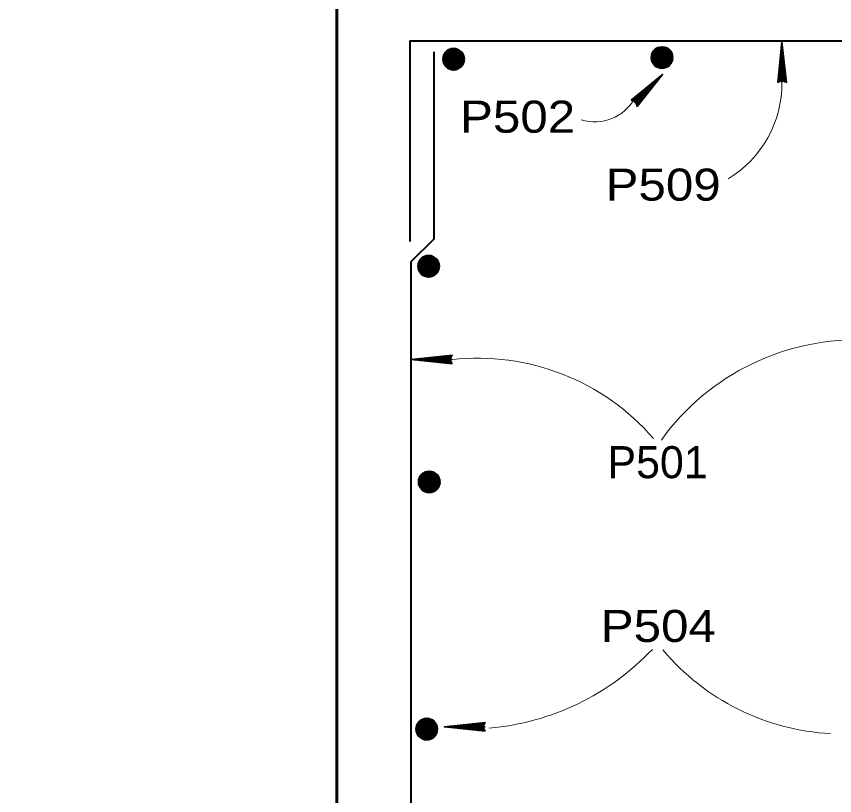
# Model space of a CAD drawing. Extents: x 14.14 to 17.34, y -1.61 to 0.38.
# Drawn here: x 15.5046 to 15.7173, y -1.0834 to -0.8807 of the extents above; entities that cross this region are included whole.
import ezdxf

# ---------------------------------------------------------------- set-up
doc = ezdxf.new("R2010")
doc.units = 0
doc.header["$LTSCALE"] = 0.0033
doc.layers.add('1', color=7, linetype='Continuous', lineweight=40)

msp = doc.modelspace()

# ---------------------------------------------------------------- linework, layer by layer
at = {"layer": '1'}
for p, q in [((15.67475, -0.89025), (15.6735, -0.889083)), ((15.616167, -0.890333), (15.62075, -0.8925)), ((15.616417, -0.89075), (15.620333, -0.8915)), ((15.616417, -0.890917), (15.620333, -0.891667)), ((15.616417, -0.891167), (15.62025, -0.891917)), ((15.6165, -0.890333), (15.620417, -0.891)), ((15.6165, -0.8905), (15.620417, -0.89125)), ((15.616583, -0.89), (15.620417, -0.890667)), ((15.6185, -0.890833), (15.619833, -0.889833)), ((15.620583, -0.890667), (15.619333, -0.8895)), ((15.670333, -0.889917), (15.674917, -0.892083)), ((15.6705, -0.890917), (15.674333, -0.891583)), ((15.6705, -0.891083), (15.674333, -0.891833)), ((15.670583, -0.890333), (15.6745, -0.891083)), ((15.670583, -0.8905), (15.6745, -0.89125)), ((15.670583, -0.89075), (15.674417, -0.8915)), ((15.670667, -0.889917), (15.674583, -0.890583)), ((15.670667, -0.890083), (15.674583, -0.890833)), ((15.67075, -0.889583), (15.674583, -0.89025)), ((15.672667, -0.890417), (15.674, -0.889417)), ((15.616, -0.893083), (15.619833, -0.893833)), ((15.616, -0.89325), (15.619833, -0.894)), ((15.616083, -0.892583), (15.62, -0.893333)), ((15.616083, -0.89275), (15.619917, -0.8935)), ((15.616083, -0.893), (15.619917, -0.893667)), ((15.616167, -0.892167), (15.620083, -0.892917)), ((15.61625, -0.89175), (15.620083, -0.8925)), ((15.61625, -0.891917), (15.620083, -0.892667)), ((15.616333, -0.891333), (15.620167, -0.892)), ((15.616333, -0.8915), (15.620167, -0.89225)), ((15.670167, -0.892667), (15.674, -0.893417)), ((15.670167, -0.892833), (15.674, -0.893583)), ((15.67025, -0.892167), (15.674167, -0.892917)), ((15.67025, -0.892333), (15.674083, -0.893083)), ((15.67025, -0.892583), (15.674083, -0.89325)), ((15.670333, -0.89175), (15.67425, -0.8925)), ((15.670417, -0.891333), (15.67425, -0.892083)), ((15.670417, -0.8915), (15.67425, -0.89225)), ((15.6745, -0.893083), (15.67075, -0.8935)), ((15.620333, -0.8935), (15.616583, -0.893917)), ((15.609667, -0.944167), (15.61425, -0.946333)), ((15.61, -0.944167), (15.613917, -0.944833)), ((15.61, -0.944333), (15.613917, -0.945083)), ((15.610083, -0.943833), (15.613917, -0.9445)), ((15.612, -0.944667), (15.613333, -0.943667)), ((15.614083, -0.9445), (15.612833, -0.943333)), ((15.609583, -0.946417), (15.6135, -0.947167)), ((15.609667, -0.946), (15.613583, -0.94675)), ((15.60975, -0.945583), (15.613583, -0.946333)), ((15.60975, -0.94575), (15.613583, -0.9465)), ((15.609833, -0.945167), (15.613667, -0.945833)), ((15.609833, -0.945333), (15.613667, -0.946083)), ((15.609917, -0.944583), (15.613833, -0.945333)), ((15.609917, -0.94475), (15.613833, -0.9455)), ((15.609917, -0.945), (15.61375, -0.94575)), ((15.6095, -0.946917), (15.613333, -0.947667)), ((15.6095, -0.947083), (15.613333, -0.947833)), ((15.609583, -0.946583), (15.613417, -0.947333)), ((15.609583, -0.946833), (15.613417, -0.9475)), ((15.613833, -0.947333), (15.610083, -0.94775)), ((15.61425, -1.000583), (15.613, -0.999417)), ((15.609833, -1.00025), (15.614417, -1.002417)), ((15.609917, -1.001667), (15.61375, -1.002417)), ((15.609917, -1.001833), (15.61375, -1.002583)), ((15.61, -1.00125), (15.613833, -1.001917)), ((15.61, -1.001417), (15.613833, -1.002167)), ((15.610083, -1.000667), (15.614, -1.001417)), ((15.610083, -1.000833), (15.614, -1.001583)), ((15.610083, -1.001083), (15.613917, -1.001833)), ((15.610167, -1.00025), (15.614083, -1.000917)), ((15.610167, -1.000417), (15.614083, -1.001167)), ((15.61025, -0.999917), (15.614083, -1.000583)), ((15.612167, -1.00075), (15.6135, -0.99975)), ((15.609667, -1.003), (15.6135, -1.00375)), ((15.609667, -1.003167), (15.6135, -1.003917)), ((15.60975, -1.0025), (15.613667, -1.00325)), ((15.60975, -1.002667), (15.613583, -1.003417)), ((15.60975, -1.002917), (15.613583, -1.003583)), ((15.609833, -1.002083), (15.61375, -1.002833)), ((15.614, -1.003417), (15.61025, -1.003833)), ((15.609167, -1.0645), (15.61375, -1.066667)), ((15.609333, -1.0655), (15.613167, -1.066167)), ((15.609333, -1.065667), (15.613167, -1.066417)), ((15.609417, -1.064917), (15.613333, -1.065667)), ((15.609417, -1.065083), (15.613333, -1.065833)), ((15.609417, -1.065333), (15.61325, -1.066083)), ((15.6095, -1.0645), (15.613417, -1.065167)), ((15.6095, -1.064667), (15.613417, -1.065417)), ((15.609583, -1.064167), (15.613417, -1.064833)), ((15.6115, -1.065), (15.612833, -1.064)), ((15.613583, -1.064833), (15.612333, -1.063667)), ((15.609, -1.06725), (15.612833, -1.068)), ((15.609, -1.067417), (15.612833, -1.068167)), ((15.609083, -1.06675), (15.613, -1.0675)), ((15.609083, -1.066917), (15.612917, -1.067667)), ((15.609083, -1.067167), (15.612917, -1.067833)), ((15.609167, -1.066333), (15.613083, -1.067083)), ((15.60925, -1.065917), (15.613083, -1.066667)), ((15.60925, -1.066083), (15.613083, -1.066833)), ((15.613333, -1.067667), (15.609583, -1.068083))]:
    msp.add_line(p, q, dxfattribs=at)
at = {"layer": '1', "lineweight": 35}
for p, q in [((15.703583, -0.897917), (15.703583, -0.887333)), ((15.702583, -0.897667), (15.7035, -0.889833)), ((15.702583, -0.897667), (15.7035, -0.889833)), ((15.702667, -0.897667), (15.7035, -0.889833)), ((15.70275, -0.897667), (15.703583, -0.889833)), ((15.70275, -0.897667), (15.70375, -0.889833)), ((15.70425, -0.89775), (15.7035, -0.890417)), ((15.704417, -0.897667), (15.703583, -0.890333)), ((15.7045, -0.897667), (15.70375, -0.890333)), ((15.704667, -0.897667), (15.703833, -0.890333)), ((15.664583, -0.902417), (15.67075, -0.8975)), ((15.664583, -0.902417), (15.67075, -0.8975)), ((15.664583, -0.9025), (15.67075, -0.8975)), ((15.665167, -0.90325), (15.672583, -0.895833)), ((15.664667, -0.902583), (15.670833, -0.897667)), ((15.664667, -0.902583), (15.671, -0.897667)), ((15.66575, -0.903583), (15.670333, -0.897917)), ((15.665917, -0.90375), (15.6705, -0.898)), ((15.665917, -0.90375), (15.670583, -0.898083)), ((15.666, -0.903917), (15.670667, -0.898083)), ((15.617583, -0.970833), (15.60975, -0.969833)), ((15.617583, -0.968917), (15.61025, -0.96975)), ((15.617583, -0.969083), (15.61025, -0.969833)), ((15.617583, -0.969167), (15.61025, -0.97)), ((15.617667, -0.969333), (15.610333, -0.970083)), ((15.617833, -0.97), (15.60725, -0.97)), ((15.617583, -0.970833), (15.60975, -0.97)), ((15.617583, -0.971), (15.60975, -0.970083)), ((15.617583, -0.971), (15.60975, -0.970083)), ((15.617583, -0.970917), (15.60975, -0.970083)), ((15.626417, -1.0655), (15.615833, -1.0655)), ((15.626167, -1.066333), (15.618333, -1.065333)), ((15.626167, -1.066333), (15.618333, -1.0655)), ((15.626167, -1.0665), (15.618333, -1.065583)), ((15.626167, -1.0665), (15.618333, -1.065583)), ((15.626167, -1.066417), (15.618333, -1.065583)), ((15.626167, -1.064417), (15.618833, -1.06525)), ((15.626167, -1.064583), (15.618833, -1.065333)), ((15.626167, -1.064667), (15.618833, -1.0655)), ((15.62625, -1.064833), (15.618917, -1.065583))]:
    msp.add_line(p, q, dxfattribs=at)
at = {"layer": '1', "lineweight": 60}
for p, q in [((15.616417, -0.890333), (15.61625, -0.89325)), ((15.616667, -0.890333), (15.616417, -0.89325)), ((15.616833, -0.890333), (15.616667, -0.893333)), ((15.617, -0.890333), (15.61675, -0.893333)), ((15.617167, -0.890333), (15.617, -0.893333)), ((15.617417, -0.890333), (15.61725, -0.893333)), ((15.617667, -0.890333), (15.617417, -0.893333)), ((15.61775, -0.890417), (15.617583, -0.893333)), ((15.617917, -0.890417), (15.61775, -0.893333)), ((15.618083, -0.890417), (15.617917, -0.893333)), ((15.618333, -0.890417), (15.618083, -0.893333)), ((15.6185, -0.890417), (15.618333, -0.893333)), ((15.61875, -0.8905), (15.6185, -0.893417)), ((15.619, -0.8905), (15.61875, -0.893417)), ((15.619167, -0.8905), (15.619, -0.893417)), ((15.61925, -0.8905), (15.619083, -0.893417)), ((15.619417, -0.8905), (15.61925, -0.893417)), ((15.6195, -0.8905), (15.619333, -0.893417)), ((15.61975, -0.890583), (15.6195, -0.8935)), ((15.619917, -0.890583), (15.61975, -0.8935)), ((15.620083, -0.890583), (15.619833, -0.8935)), ((15.62025, -0.890583), (15.620083, -0.8935)), ((15.6205, -0.890583), (15.620333, -0.8935)), ((15.62075, -0.8925), (15.620583, -0.890667)), ((15.670583, -0.889917), (15.670417, -0.892833)), ((15.670833, -0.889917), (15.670583, -0.892833)), ((15.671, -0.889917), (15.670833, -0.892917)), ((15.671167, -0.889917), (15.670917, -0.892917)), ((15.671333, -0.889917), (15.671167, -0.892917)), ((15.671583, -0.889917), (15.671417, -0.892917)), ((15.671833, -0.889917), (15.671583, -0.892917)), ((15.671917, -0.89), (15.67175, -0.892917)), ((15.672083, -0.89), (15.671917, -0.892917)), ((15.67225, -0.89), (15.672083, -0.892917)), ((15.6725, -0.89), (15.67225, -0.892917)), ((15.672667, -0.89), (15.6725, -0.892917)), ((15.672917, -0.890083), (15.672667, -0.893)), ((15.673167, -0.890083), (15.672917, -0.893)), ((15.673333, -0.890083), (15.673167, -0.893)), ((15.673417, -0.890083), (15.67325, -0.893)), ((15.673583, -0.890083), (15.673417, -0.893)), ((15.673667, -0.890083), (15.6735, -0.893)), ((15.673917, -0.890167), (15.673667, -0.893083)), ((15.674083, -0.890167), (15.673917, -0.893083)), ((15.67425, -0.890167), (15.674, -0.893083)), ((15.674417, -0.890167), (15.67425, -0.893083)), ((15.674667, -0.890167), (15.6745, -0.893083)), ((15.674917, -0.892083), (15.67475, -0.89025)), ((15.62075, -0.8925), (15.616, -0.89325)), ((15.674917, -0.892083), (15.670167, -0.892833)), ((15.609917, -0.944167), (15.60975, -0.947083)), ((15.610167, -0.944167), (15.609917, -0.947083)), ((15.610333, -0.944167), (15.610167, -0.947167)), ((15.6105, -0.944167), (15.61025, -0.947167)), ((15.610667, -0.944167), (15.6105, -0.947167)), ((15.610917, -0.944167), (15.61075, -0.947167)), ((15.611167, -0.944167), (15.610917, -0.947167)), ((15.61125, -0.94425), (15.611083, -0.947167)), ((15.611417, -0.94425), (15.61125, -0.947167)), ((15.611583, -0.94425), (15.611417, -0.947167)), ((15.611833, -0.94425), (15.611583, -0.947167)), ((15.612, -0.94425), (15.611833, -0.947167)), ((15.61225, -0.944333), (15.612, -0.94725)), ((15.6125, -0.944333), (15.61225, -0.94725)), ((15.612667, -0.944333), (15.6125, -0.94725)), ((15.61275, -0.944333), (15.612583, -0.94725)), ((15.612917, -0.944333), (15.61275, -0.94725)), ((15.613, -0.944333), (15.612833, -0.94725)), ((15.61325, -0.944417), (15.613, -0.947333)), ((15.613417, -0.944417), (15.61325, -0.947333)), ((15.613583, -0.944417), (15.613333, -0.947333)), ((15.61375, -0.944417), (15.613583, -0.947333)), ((15.614, -0.944417), (15.613833, -0.947333)), ((15.61425, -0.946333), (15.6095, -0.947083)), ((15.61425, -0.946333), (15.614083, -0.9445)), ((15.610083, -1.00025), (15.609917, -1.003167)), ((15.610333, -1.00025), (15.610083, -1.003167)), ((15.6105, -1.00025), (15.610333, -1.00325)), ((15.610667, -1.00025), (15.610417, -1.00325)), ((15.610833, -1.00025), (15.610667, -1.00325)), ((15.611083, -1.00025), (15.610917, -1.00325)), ((15.611333, -1.00025), (15.611083, -1.00325)), ((15.611417, -1.000333), (15.61125, -1.00325)), ((15.611583, -1.000333), (15.611417, -1.00325)), ((15.61175, -1.000333), (15.611583, -1.00325)), ((15.612, -1.000333), (15.61175, -1.00325)), ((15.612167, -1.000333), (15.612, -1.00325)), ((15.612417, -1.000417), (15.612167, -1.003333)), ((15.612667, -1.000417), (15.612417, -1.003333)), ((15.612833, -1.000417), (15.612667, -1.003333)), ((15.612917, -1.000417), (15.61275, -1.003333)), ((15.613083, -1.000417), (15.612917, -1.003333)), ((15.613167, -1.000417), (15.613, -1.003333)), ((15.613417, -1.0005), (15.613167, -1.003417)), ((15.613583, -1.0005), (15.613417, -1.003417)), ((15.61375, -1.0005), (15.6135, -1.003417)), ((15.613917, -1.0005), (15.61375, -1.003417)), ((15.614167, -1.0005), (15.614, -1.003417)), ((15.614417, -1.002417), (15.61425, -1.000583)), ((15.614417, -1.002417), (15.609667, -1.003167)), ((15.609417, -1.0645), (15.60925, -1.067417)), ((15.609667, -1.0645), (15.609417, -1.067417)), ((15.609833, -1.0645), (15.609667, -1.0675)), ((15.61, -1.0645), (15.60975, -1.0675)), ((15.610167, -1.0645), (15.61, -1.0675)), ((15.610417, -1.0645), (15.61025, -1.0675)), ((15.610667, -1.0645), (15.610417, -1.0675)), ((15.61075, -1.064583), (15.610583, -1.0675)), ((15.610917, -1.064583), (15.61075, -1.0675)), ((15.611083, -1.064583), (15.610917, -1.0675)), ((15.611333, -1.064583), (15.611083, -1.0675)), ((15.6115, -1.064583), (15.611333, -1.0675)), ((15.61175, -1.064667), (15.6115, -1.067583)), ((15.612, -1.064667), (15.61175, -1.067583)), ((15.612167, -1.064667), (15.612, -1.067583)), ((15.61225, -1.064667), (15.612083, -1.067583)), ((15.612417, -1.064667), (15.61225, -1.067583)), ((15.6125, -1.064667), (15.612333, -1.067583)), ((15.61275, -1.06475), (15.6125, -1.067667)), ((15.612917, -1.06475), (15.61275, -1.067667)), ((15.613083, -1.06475), (15.612833, -1.067667)), ((15.61325, -1.06475), (15.613083, -1.067667)), ((15.6135, -1.06475), (15.613333, -1.067667)), ((15.61375, -1.066667), (15.613583, -1.064833)), ((15.61375, -1.066667), (15.609, -1.067417))]:
    msp.add_line(p, q, dxfattribs=at)
for points in [[(15.504583, -1.202667), (15.587917, -1.202667), (15.587917, -0.869333), (15.754583, -0.869333), (15.754583, -1.202667), (15.837917, -1.202667)], [(15.674, -0.893583), (15.674, -0.889417), (15.672333, -0.894083), (15.672833, -0.888917), (15.67075, -0.8935), (15.6715, -0.889), (15.673083, -0.894), (15.669917, -0.890667), (15.67475, -0.89025), (15.6715, -0.893917), (15.6735, -0.889083), (15.670333, -0.889917), (15.670167, -0.892833)], [(15.67075, -0.8935), (15.67225, -0.89125), (15.670083, -0.890333), (15.672083, -0.888917), (15.67225, -0.891167), (15.673917, -0.8935), (15.669917, -0.891167), (15.672667, -0.890417)], [(15.6735, -0.889083), (15.67225, -0.89125), (15.6745, -0.893083)], [(15.615583, -0.892), (15.62075, -0.891333), (15.616167, -0.890333)], [(15.619833, -0.894), (15.619833, -0.889833), (15.618167, -0.8945), (15.618667, -0.889333), (15.616583, -0.893917), (15.617333, -0.889417), (15.618917, -0.894417), (15.61575, -0.891083), (15.620583, -0.890667), (15.617333, -0.894333), (15.619333, -0.8895), (15.616167, -0.890333), (15.616, -0.89325)], [(15.616583, -0.893917), (15.618083, -0.891667), (15.615917, -0.89075), (15.617917, -0.889333), (15.618083, -0.891583), (15.61975, -0.893917), (15.61575, -0.891583), (15.6185, -0.890833)], [(15.619333, -0.8895), (15.618083, -0.891667), (15.620333, -0.8935)], [(15.66975, -0.891583), (15.674917, -0.890917), (15.670333, -0.889917)], [(15.609083, -0.945833), (15.61425, -0.945167), (15.609667, -0.944167)], [(15.613333, -0.947833), (15.613333, -0.943667), (15.611667, -0.948333), (15.612167, -0.943167), (15.610083, -0.94775), (15.610833, -0.94325), (15.612417, -0.94825), (15.60925, -0.944917), (15.614083, -0.9445), (15.610833, -0.948167), (15.612833, -0.943333), (15.609667, -0.944167), (15.6095, -0.947083)], [(15.610083, -0.94775), (15.611583, -0.9455), (15.609417, -0.944583), (15.611417, -0.943167), (15.611583, -0.945417), (15.61325, -0.94775), (15.60925, -0.945417), (15.612, -0.944667)], [(15.612833, -0.943333), (15.611583, -0.9455), (15.613833, -0.947333)], [(15.6135, -1.003917), (15.6135, -0.99975), (15.611833, -1.004417), (15.612333, -0.99925), (15.61025, -1.003833), (15.611, -0.999333), (15.612583, -1.004333), (15.609417, -1.001), (15.61425, -1.000583), (15.611, -1.00425), (15.613, -0.999417), (15.609833, -1.00025), (15.609667, -1.003167)], [(15.61025, -1.003833), (15.61175, -1.001583), (15.609583, -1.000667), (15.611583, -0.99925), (15.61175, -1.0015), (15.613417, -1.003833), (15.609417, -1.0015), (15.612167, -1.00075)], [(15.613, -0.999417), (15.61175, -1.001583), (15.614, -1.003417)], [(15.60925, -1.001917), (15.614417, -1.00125), (15.609833, -1.00025)], [(15.612833, -1.068167), (15.612833, -1.064), (15.611167, -1.068667), (15.611667, -1.0635), (15.609583, -1.068083), (15.610333, -1.063583), (15.611917, -1.068583), (15.60875, -1.06525), (15.613583, -1.064833), (15.610333, -1.0685), (15.612333, -1.063667), (15.609167, -1.0645), (15.609, -1.067417)], [(15.609583, -1.068083), (15.611083, -1.065833), (15.608917, -1.064917), (15.610917, -1.0635), (15.611083, -1.06575), (15.61275, -1.068083), (15.60875, -1.06575), (15.6115, -1.065)], [(15.608583, -1.066167), (15.61375, -1.0655), (15.609167, -1.0645)], [(15.612333, -1.063667), (15.611083, -1.065833), (15.613333, -1.067667)]]:
    msp.add_lwpolyline(points, dxfattribs=at)
at = {"layer": '1'}
for points in [[(15.606917, -0.939333), (15.606917, -0.887083), (15.736583, -0.887083), (15.736583, -0.939667)], [(15.613083, -0.89), (15.613083, -0.938667), (15.607167, -0.944583), (15.607167, -1.152917), (15.613083, -1.158833), (15.613083, -1.188833)], [(15.616, -0.89325), (15.618083, -0.8945), (15.619833, -0.894), (15.62075, -0.8925)], [(15.670167, -0.892833), (15.67225, -0.894083), (15.674, -0.893583), (15.674917, -0.892083)], [(15.6095, -0.947083), (15.611583, -0.948333), (15.613333, -0.947833), (15.61425, -0.946333)], [(15.609667, -1.003167), (15.61175, -1.004417), (15.6135, -1.003917), (15.614417, -1.002417)], [(15.609, -1.067417), (15.611083, -1.068667), (15.612833, -1.068167), (15.61375, -1.066667)]]:
    msp.add_lwpolyline(points, dxfattribs=at)
at = {"layer": '1', "lineweight": 35}
for points in [[(15.7025, -0.897917), (15.703583, -0.887333), (15.70475, -0.897917), (15.703583, -0.897333)], [(15.7035, -0.897167), (15.703417, -0.8925), (15.7035, -0.8925), (15.7035, -0.893417), (15.703417, -0.897167), (15.703333, -0.894167), (15.70325, -0.897333), (15.703167, -0.895083), (15.703083, -0.897333), (15.703333, -0.893833), (15.7035, -0.889167), (15.70375, -0.890083), (15.70375, -0.888833), (15.70375, -0.897167), (15.703917, -0.89475), (15.703917, -0.897333), (15.7035, -0.892), (15.704167, -0.897333)], [(15.664417, -0.902583), (15.672583, -0.895833), (15.665917, -0.904167), (15.6655, -0.902917)], [(15.665583, -0.90275), (15.668833, -0.899333), (15.668917, -0.8995), (15.66825, -0.900083), (15.6655, -0.902667), (15.667583, -0.9005), (15.665333, -0.90275), (15.666833, -0.901083), (15.665167, -0.902583), (15.667833, -0.900333), (15.671167, -0.897167), (15.67075, -0.897917), (15.671667, -0.897083), (15.66575, -0.902917), (15.667583, -0.901333), (15.66575, -0.903167), (15.66925, -0.899), (15.666, -0.903333)], [(15.617833, -0.971083), (15.60725, -0.97), (15.617833, -0.968833), (15.61725, -0.97)], [(15.617083, -0.970083), (15.612417, -0.970167), (15.612417, -0.970083), (15.613333, -0.970083), (15.617083, -0.970167), (15.614083, -0.97025), (15.61725, -0.970333), (15.615, -0.970417), (15.61725, -0.9705), (15.61375, -0.97025), (15.609083, -0.970083), (15.61, -0.969833), (15.60875, -0.969833), (15.617083, -0.969833), (15.614667, -0.969667), (15.61725, -0.969667), (15.611917, -0.970083), (15.61725, -0.969417)], [(15.626417, -1.066583), (15.615833, -1.0655), (15.626417, -1.064333), (15.625833, -1.0655)], [(15.625667, -1.065583), (15.621, -1.065667), (15.621, -1.065583), (15.621917, -1.065583), (15.625667, -1.065667), (15.622667, -1.06575), (15.625833, -1.065833), (15.623583, -1.065917), (15.625833, -1.066), (15.622333, -1.06575), (15.617667, -1.065583), (15.618583, -1.065333), (15.617333, -1.065333), (15.625667, -1.065333), (15.62325, -1.065167), (15.625833, -1.065167), (15.6205, -1.065583), (15.625833, -1.064917)]]:
    msp.add_lwpolyline(points, close=True, dxfattribs=at)
for points in [[(15.7035, -0.897167), (15.70275, -0.897583), (15.703, -0.897333), (15.703333, -0.897167), (15.70325, -0.896917), (15.702917, -0.897083), (15.703667, -0.89725), (15.704167, -0.897417), (15.704583, -0.897667)], [(15.665583, -0.90275), (15.66475, -0.9025), (15.665083, -0.9025), (15.665417, -0.902583), (15.665583, -0.902333), (15.66525, -0.90225), (15.665667, -0.902917), (15.665917, -0.903417), (15.665917, -0.903833)], [(15.617083, -0.970083), (15.6175, -0.970833), (15.61725, -0.970583), (15.617083, -0.97025), (15.616833, -0.970333), (15.617, -0.970667), (15.617167, -0.969917), (15.617333, -0.969417), (15.617583, -0.969)], [(15.625667, -1.065583), (15.626083, -1.066333), (15.625833, -1.066083), (15.625667, -1.06575), (15.625417, -1.065833), (15.625583, -1.066167), (15.62575, -1.065417), (15.625917, -1.064917), (15.626167, -1.0645)]]:
    msp.add_lwpolyline(points, dxfattribs=at)
at = {"layer": '1', "lineweight": 60}
for centre in [(15.672417, -0.891483), (15.61825, -0.8919), (15.61175, -0.945733), (15.611917, -1.001817), (15.61125, -1.066067)]:
    msp.add_circle(centre, 0.00264, dxfattribs=at)
at = {"layer": '1', "lineweight": 13}
for centre, radius, start, end in [((15.674575, -0.898175), 0.029009, 301.15475, 0.51002), ((15.654913, -0.896246), 0.011944, 252.97794, 330.74313), ((15.723056, -1.027389), 0.062542, 87.30189, 144.32616), ((15.624547, -1.02991), 0.060285, 40.82327, 96.39421), ((15.621712, -0.999726), 0.06636, 275.00335, 316.58566), ((15.719464, -1.006268), 0.061067, 219.97438, 266.98319)]:
    msp.add_arc(centre, radius, start, end, dxfattribs=at)

# ---------------------------------------------------------------- texts
at = {"layer": '1', "width": 1.15}
for s, height, p in [('P502', 0.008333, (15.619917, -0.911)), ('P509', 0.008334, (15.65775, -0.928667)), ('P504', 0.008333, (15.6565, -1.043417))]:
    msp.add_text(s, height=height, dxfattribs=at).set_placement(p)
at = {"layer": '1'}
msp.add_text('P501', height=0.008333, dxfattribs=at).set_placement((15.65825, -1.000833))

doc.saveas('drawing.dxf')
